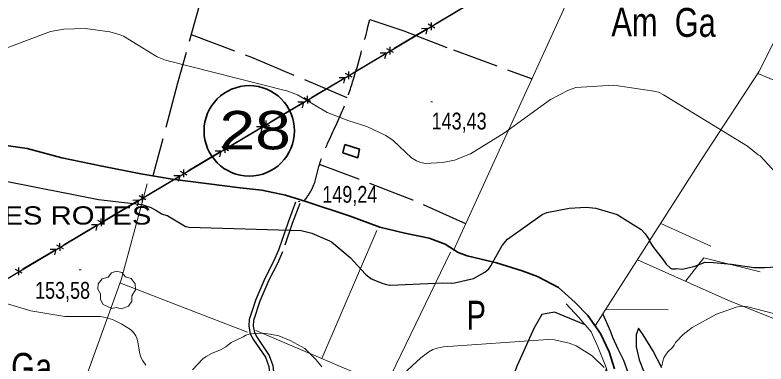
# Model space of a CAD drawing. Extents: x 483840 to 488445, y 4386047 to 4389027.
# Drawn here: x 484357.8 to 484749, y 4386720.2 to 4386901.9 of the extents above; entities that cross this region are included whole.
import ezdxf
from ezdxf.enums import TextEntityAlignment as Align

# ---------------------------------------------------------------- set-up
doc = ezdxf.new("R2010")
doc.units = 0
doc.header["$LTSCALE"] = 4
doc.linetypes.add('LONG_DASHED', pattern=[7.5, 6, -1.5])
doc.linetypes.add('MEDIUM_DASHED', pattern=[4.5, 3, -1.5])
for name, color, linetype, lineweight in [('13', 7, 'Continuous', 25), ('25', 7, 'LONG_DASHED', 25), ('29', 7, 'Continuous', 13), ('38', 7, 'Continuous', 25), ('43', 7, 'Continuous', 25), ('47', 7, 'Continuous', 35), ('51', 7, 'Continuous', 13), ('6', 7, 'Continuous', 35), ('7', 7, 'Continuous', 13), ('8', 7, 'Continuous', 25), ('9', 7, 'Continuous', 13)]:
    doc.layers.add(name, color=color, linetype=linetype, lineweight=lineweight)
doc.layers.add('31', color=7, linetype='Continuous')
doc.layers.add('5', color=7, linetype='Continuous')

msp = doc.modelspace()

# ---------------------------------------------------------------- linework, layer by layer
at = {"layer": '25'}
for points in [[(484466.34, 4386950.92), (484455.07, 4386911.29), (484442.52, 4386866.46), (484429.61, 4386818.2)], [(484542.67, 4386899.52), (484560.41, 4386893.61), (484586.19, 4386883.73), (484627.1, 4386868.71)], [(484449.61, 4386891.77), (484480.98, 4386880.01), (484530.97, 4386858.79)], [(484592.57, 4386793.23), (484565.05, 4386805.51), (484536.91, 4386816.5), (484516.47, 4386824.02)], [(484654.75, 4386740.67), (484638.84, 4386747.11), (484632.18, 4386745.98), (484628.03, 4386738.64), (484624.29, 4386730.24), (484619.44, 4386719.48), (484616.41, 4386711.81), (484614.12, 4386702.47), (484612.34, 4386696.36), (484613.55, 4386692.23), (484621.74, 4386688.28), (484632.4, 4386684.67), (484643.19, 4386680.71), (484655.15, 4386675.55), (484659.12, 4386681.58), (484662.51, 4386695.9), (484663.39, 4386702.96), (484663.97, 4386706.18), (484665.84, 4386717.94)], [(484677.17, 4386715.7), (484674.94, 4386722.03), (484672.03, 4386727.86), (484669.18, 4386733.98), (484668.35, 4386736.5), (484668.41, 4386736.5), (484667.38, 4386738.59), (484664.04, 4386746.35)], [(484694.65, 4386718.22), (484690.11, 4386727.3), (484684.93, 4386735.35), (484682.56, 4386738.82), (484681.41, 4386735.45), (484681.27, 4386729.21), (484682.86, 4386722.41), (484685.58, 4386715.77)]]:
    msp.add_lwpolyline(points, dxfattribs=at)
at = {"layer": '29'}
msp.add_lwpolyline([(484408.26, 4386749.08), (484403.72, 4386751.2), (484402.31, 4386753.74), (484402.41, 4386756.72), (484401.04, 4386759.13), (484401.08, 4386761.88), (484403.24, 4386764.48), (484406.43, 4386765.48), (484408.08, 4386767.67), (484410.65, 4386768.5), (484413.51, 4386767.85), (484415.46, 4386765.58), (484418.27, 4386764.76), (484420.4, 4386761.91), (484420.64, 4386758.78), (484418.76, 4386755.63), (484418.76, 4386752.95), (484416.94, 4386750.34), (484413.32, 4386749), (484410.55, 4386749.63)], close=True, dxfattribs=at)
at = {"layer": '38'}
msp.add_lwpolyline([(484503.94, 4386804.39), (484500.14, 4386794.1), (484495.04, 4386779.48), (484492.44, 4386773.52), (484487.95, 4386764.75), (484483.27, 4386753.75), (484479.76, 4386743.29), (484479.64, 4386739.82), (484480.35, 4386735.84), (484482.04, 4386732.77), (484488.27, 4386723.67), (484489.97, 4386718.91), (484490.51, 4386712.77), (484490.38, 4386704.96), (484489.34, 4386692.14), (484488.04, 4386679.23), (484487.01, 4386669.77), (484484.32, 4386659.38), (484475.55, 4386632.97), (484472.4, 4386624.43), (484469.99, 4386619), (484467.68, 4386613.52)], dxfattribs=at)
at = {"layer": '38', "linetype": 'MEDIUM_DASHED'}
msp.add_lwpolyline([(484506.1, 4386803.76), (484502.25, 4386793.34), (484497.14, 4386778.66), (484494.47, 4386772.56), (484489.99, 4386763.8), (484485.37, 4386752.95), (484481.99, 4386742.89), (484481.89, 4386739.98), (484482.5, 4386736.6), (484483.96, 4386733.94), (484490.29, 4386724.69), (484492.18, 4386719.4), (484492.76, 4386712.85), (484492.63, 4386704.85), (484491.58, 4386691.94), (484490.27, 4386678.99), (484489.23, 4386669.37), (484486.49, 4386658.74), (484477.67, 4386632.22), (484474.48, 4386623.58), (484472.05, 4386618.11), (484469.75, 4386612.65)], dxfattribs=at)
at = {"layer": '38', "linetype": 'LONG_DASHED'}
msp.add_spline([(484508.56, 4386805.15), (484512.89, 4386812.09), (484516.13, 4386823.07), (484520.66, 4386835.07), (484529.22, 4386854.19), (484534.27, 4386868.96), (484542.67, 4386899.52)], degree=3, dxfattribs=at)
at = {"layer": '43'}
for p, q in [((484576.87, 4386897.38), (484594.06, 4386907.59)), ((484574.75, 4386894.09), (484574.7, 4386898.09)), ((484555.38, 4386884.61), (484572.57, 4386894.82)), ((484572.57, 4386894.82), (484569.57, 4386894.78)), ((484572.57, 4386894.82), (484571.83, 4386891.92)), ((484576.47, 4386895.11), (484572.98, 4386897.07)), ((484554.98, 4386882.34), (484551.49, 4386884.3)), ((484553.26, 4386881.32), (484553.21, 4386885.32)), ((484533.88, 4386871.84), (484551.08, 4386882.05)), ((484551.08, 4386882.05), (484548.08, 4386882.01)), ((484551.08, 4386882.05), (484550.34, 4386879.15)), ((484533.48, 4386869.58), (484530, 4386871.53)), ((484531.76, 4386868.55), (484531.72, 4386872.55)), ((484512.39, 4386859.07), (484529.58, 4386869.28)), ((484529.58, 4386869.28), (484526.58, 4386869.24)), ((484529.58, 4386869.28), (484528.85, 4386866.38)), ((484511.99, 4386856.81), (484508.5, 4386858.76)), ((484510.27, 4386855.78), (484510.22, 4386859.78)), ((484490.9, 4386846.3), (484508.09, 4386856.51)), ((484508.09, 4386856.51), (484505.09, 4386856.48)), ((484508.09, 4386856.51), (484507.35, 4386853.61)), ((484488.78, 4386843.01), (484488.73, 4386847.01)), ((484469.41, 4386833.53), (484486.6, 4386843.74)), ((484486.6, 4386843.74), (484483.6, 4386843.71)), ((484486.6, 4386843.74), (484485.86, 4386840.84)), ((484490.5, 4386844.04), (484487.01, 4386845.99)), ((484469, 4386831.27), (484465.52, 4386833.22)), ((484467.29, 4386830.24), (484467.24, 4386834.24)), ((484447.91, 4386820.76), (484465.11, 4386830.97)), ((484465.11, 4386830.97), (484462.11, 4386830.94)), ((484465.11, 4386830.97), (484464.37, 4386828.07)), ((484447.51, 4386818.5), (484444.03, 4386820.45)), ((484445.79, 4386817.47), (484445.74, 4386821.47)), ((484426.42, 4386807.99), (484443.61, 4386818.2)), ((484443.61, 4386818.2), (484440.61, 4386818.17)), ((484443.61, 4386818.2), (484442.87, 4386815.3)), ((484424.3, 4386804.71), (484424.25, 4386808.7)), ((484404.93, 4386795.22), (484422.12, 4386805.43)), ((484422.12, 4386805.43), (484419.12, 4386805.4)), ((484422.12, 4386805.43), (484421.38, 4386802.53)), ((484426.02, 4386805.73), (484422.53, 4386807.68)), ((484383.43, 4386782.45), (484400.63, 4386792.66)), ((484400.63, 4386792.66), (484397.63, 4386792.63)), ((484400.63, 4386792.66), (484399.89, 4386789.76)), ((484404.53, 4386792.96), (484401.04, 4386794.91)), ((484402.81, 4386791.94), (484402.76, 4386795.93)), ((484383.03, 4386780.19), (484379.55, 4386782.14)), ((484381.31, 4386779.17), (484381.27, 4386783.16)), ((484361.94, 4386769.68), (484379.14, 4386779.9)), ((484379.14, 4386779.9), (484376.13, 4386779.86)), ((484379.14, 4386779.9), (484378.4, 4386776.99)), ((484361.54, 4386767.42), (484358.05, 4386769.37)), ((484359.82, 4386766.4), (484359.77, 4386770.39))]:
    msp.add_line(p, q, dxfattribs=at)
msp.add_lwpolyline([(484106.12, 4386615.59), (484337.37, 4386755.08), (484652.95, 4386942.58)], dxfattribs=at)
at = {"layer": '47'}
msp.add_lwpolyline([(484529.68, 4386834.56), (484528.63, 4386830.19), (484536.46, 4386827.58), (484537.24, 4386832.11)], close=True, dxfattribs=at)
at = {"layer": '51'}
for p, q in [((484648.28, 4386915.02), (484586.21, 4386779.34)), ((484694.15, 4386793.37), (484720.21, 4386781.48)), ((484517.63, 4386723.02), (484546.34, 4386789.79)), ((484698.01, 4386748.38), (484665.44, 4386748.54))]:
    msp.add_line(p, q, dxfattribs=at)
for points in [[(484804.18, 4386983.14), (484753.23, 4386888.09), (484745.19, 4386872.4), (484715.09, 4386826.08), (484659.98, 4386740.02)], [(484894.4, 4386807.22), (484830.58, 4386833.62), (484780.55, 4386856.53), (484744.63, 4386871.53)], [(484426.66, 4386813.96), (484413.06, 4386763.95), (484393.76, 4386710.28), (484380.34, 4386660.15), (484360.41, 4386600.63)], [(484584.64, 4386778.48), (484550.96, 4386708.8), (484483.24, 4386737.68)], [(484682.05, 4386774.47), (484729.15, 4386753.42), (484778.31, 4386733.64), (484855.29, 4386702.06)], [(484745.99, 4386768.23), (484716.52, 4386775.5), (484707.17, 4386763.53)], [(484478.91, 4386736.7), (484446.54, 4386749.35), (484412.5, 4386762.39)], [(484670.52, 4386678.94), (484670.94, 4386687.57), (484671.39, 4386693.7), (484671.01, 4386698.42), (484667.94, 4386709.51), (484665.71, 4386718.41), (484661.52, 4386728.83), (484657.91, 4386736.93), (484651.53, 4386744.47), (484644.81, 4386751.58)]]:
    msp.add_lwpolyline(points, dxfattribs=at)
at = {"layer": '6'}
msp.add_lwpolyline([(484351.99, 4386834.18), (484364.12, 4386832.42), (484382.29, 4386827.59), (484402.33, 4386823.45), (484423.29, 4386819.3), (484439.77, 4386816.4), (484475.05, 4386811.94), (484486.31, 4386810.65), (484498.67, 4386808.05), (484509.39, 4386804.9), (484532.44, 4386797.25), (484547.84, 4386791.37), (484560.89, 4386788.41), (484573.56, 4386785.73), (484581.82, 4386782.58), (484588.73, 4386778.34), (484593.26, 4386776.54), (484608.53, 4386772.83), (484621.89, 4386768.75), (484629.95, 4386765.83), (484640.85, 4386759.96), (484649.61, 4386752.18), (484656.1, 4386745.44), (484662.74, 4386736.14), (484667.21, 4386726.6), (484670.12, 4386717.75)], dxfattribs=at)
msp.add_circle((484479.83, 4386841.59), 23.55, dxfattribs=at)
at = {"layer": '7'}
for p, q in [((484574.34, 4386856.69), (484575.34, 4386856.69)), ((484505.23, 4386804.76), (484506.23, 4386804.76)), ((484391.33, 4386769.22), (484392.33, 4386769.22))]:
    msp.add_line(p, q, dxfattribs=at)
at = {"layer": '8'}
for points in [[(484337.05, 4386818.59), (484383.87, 4386809.39), (484383.89, 4386809.39), (484401.32, 4386805.87), (484423.92, 4386803.25), (484428.62, 4386801.67), (484431.16, 4386800.27), (484433.96, 4386798.54), (484434.22, 4386798.43), (484436.83, 4386797.56), (484437.13, 4386797.5), (484437.25, 4386797.49), (484437.28, 4386797.48), (484437.3, 4386797.47), (484437.39, 4386797.4), (484446.12, 4386792.07), (484446.65, 4386791.83), (484446.77, 4386791.81), (484446.81, 4386791.83), (484446.82, 4386791.83), (484446.83, 4386791.84)], [(484446.83, 4386791.84), (484446.84, 4386791.83), (484446.87, 4386791.78), (484446.99, 4386791.71), (484448.42, 4386791.37), (484506.85, 4386789.71), (484512.45, 4386788.26), (484521.71, 4386784.39), (484522.65, 4386783.88), (484532.42, 4386775.65), (484540.42, 4386766.89), (484543.15, 4386764.77), (484543.63, 4386764.48), (484543.76, 4386764.43), (484543.82, 4386764.42), (484543.85, 4386764.41), (484543.85, 4386764.4), (484543.84, 4386764.38), (484543.92, 4386764.31), (484549.4, 4386762.14), (484551.29, 4386761.58), (484553.12, 4386761.31), (484553.14, 4386761.31), (484553.15, 4386761.31), (484553.19, 4386761.3), (484580.69, 4386762.52), (484580.71, 4386762.51), (484580.73, 4386762.5), (484584.93, 4386762.29), (484584.95, 4386762.31), (484584.96, 4386762.31), (484584.99, 4386762.3), (484585.13, 4386762.29), (484586.7, 4386762.41), (484596.67, 4386764.68), (484602.48, 4386767.99), (484603.65, 4386768.88), (484604.54, 4386769.69), (484605.73, 4386771.28), (484611.56, 4386781.91), (484614.38, 4386785.16), (484632.39, 4386797.97), (484634.89, 4386799.08), (484646.38, 4386801.41), (484655.29, 4386801.88), (484660.36, 4386801.32), (484671.53, 4386797.98), (484684, 4386790.15), (484684.17, 4386790)], [(484684.17, 4386790), (484686.11, 4386787.95), (484687.32, 4386786.23), (484688.35, 4386784.68), (484688.35, 4386784.16), (484689.38, 4386782.44), (484690.41, 4386780.9), (484694.88, 4386775.22), (484696.26, 4386773.15), (484696.95, 4386772.12), (484699.01, 4386770.23), (484699.18, 4386770.06), (484699.87, 4386769.71), (484701.76, 4386769.71), (484702.11, 4386769.88), (484705.54, 4386769.54), (484711.91, 4386771.09), (484717.24, 4386773.15), (484721.54, 4386772.98), (484731, 4386772.12), (484742.69, 4386770.4), (484748.38, 4386770.47)], [(484748.38, 4386770.47), (484756.97, 4386770.92)]]:
    msp.add_lwpolyline(points, dxfattribs=at)
at = {"layer": '9'}
for points in [[(484760.08, 4386813.2), (484745.91, 4386828.65), (484745.22, 4386828.99), (484744.88, 4386829.2), (484739.41, 4386833.7), (484695.64, 4386860.44), (484692.96, 4386861.69), (484690.59, 4386862.32), (484669.7, 4386865.43), (484649.84, 4386864.25), (484646.11, 4386862.86), (484636.76, 4386857.95), (484612.73, 4386840.64), (484595.09, 4386829.66), (484586.75, 4386826.39), (484580.74, 4386825.08), (484571.51, 4386824.58), (484569.21, 4386825.08), (484566.97, 4386825.94), (484564.39, 4386827.48), (484554.76, 4386836.63), (484551.01, 4386839.18), (484541.14, 4386843.85), (484531.66, 4386846.75), (484520.39, 4386851.24), (484504.99, 4386860.34), (484500, 4386862.33), (484436.29, 4386878.4), (484431.94, 4386880.21), (484414.27, 4386890.96), (484412.69, 4386891.59), (484407.23, 4386893.13), (484394.42, 4386894.84), (484383.31, 4386894.53), (484376.33, 4386893.33), (484346.18, 4386882.06)], [(484426.06, 4386719.63), (484424.4, 4386721.8), (484423.6, 4386723.37), (484422.85, 4386725.53), (484421.66, 4386732.68), (484421.31, 4386733.72), (484420.73, 4386734.95), (484419.57, 4386736.67), (484417.91, 4386738.12), (484413.54, 4386740.93), (484408.53, 4386743.31), (484405, 4386744.44), (484402.37, 4386744.87), (484383.72, 4386745.01), (484366, 4386747.84), (484334.64, 4386757.31)], [(484862.44, 4386717.96), (484739.47, 4386750.02), (484736.93, 4386750.3), (484734.99, 4386750.19), (484733.46, 4386749.81), (484723.16, 4386746.17), (484710.44, 4386739.16), (484705.83, 4386735.51), (484701.92, 4386731.32), (484701.13, 4386730.06), (484700.25, 4386728.86), (484697.82, 4386726.54), (484696.54, 4386724.87), (484695.76, 4386723.41), (484695.17, 4386721.75), (484694.72, 4386719.28)], [(484517.61, 4386718.65), (484514.73, 4386722.42), (484508.77, 4386728.21), (484501.19, 4386732.45), (484495.23, 4386734.78), (484490.81, 4386735.78), (484486.75, 4386736.19), (484480.55, 4386735.95), (484479.84, 4386735.78), (484478.08, 4386735.15), (484476.72, 4386734.39), (484475.91, 4386734.08), (484470.45, 4386731.35), (484467.66, 4386729.2), (484464.94, 4386727.5), (484460.15, 4386725.59), (484457.44, 4386724.16), (484455.72, 4386722.83), (484450.36, 4386717.24)], [(484664.73, 4386718.46), (484658.36, 4386724.39), (484650.11, 4386729.6), (484646.42, 4386731.09), (484638.89, 4386732.72), (484635.49, 4386732.93), (484580.89, 4386729.13), (484577.71, 4386728.52), (484575.51, 4386727.74), (484573.41, 4386726.62), (484569.15, 4386723.49), (484560, 4386714.85)]]:
    msp.add_lwpolyline(points, dxfattribs=at)

# ---------------------------------------------------------------- texts
at = {"layer": '13', "width": 1.25}
msp.add_text('28', height=20, dxfattribs=at).set_placement((484482.91, 4386831.97), align=Align.CENTER)
at = {"layer": '31'}
for s, width, p in [('Am', 0.8, (484680.46, 4386890.83)), ('Ga', 0.8, (484712.13, 4386890.56)), ('P', 0.75, (484598.09, 4386738.12)), ('Ga', 0.8, (484366.52, 4386710.94))]:
    msp.add_text(s, height=15, dxfattribs=dict(at, width=width)).set_placement(p, align=Align.CENTER)
at = {"layer": '5', "width": 1.2}
msp.add_text('OLIVAR DE SES ROTES', height=9.5, dxfattribs=at).set_placement((484256.07, 4386792.8))
at = {"layer": '7', "width": 0.8}
for s, p in [('143,43', (484574.84, 4386842.32)), ('149,24', (484517.9, 4386804.15)), ('153,58', (484368.29, 4386754.18))]:
    msp.add_text(s, height=8.75, dxfattribs=at).set_placement(p)

doc.saveas('drawing.dxf')
